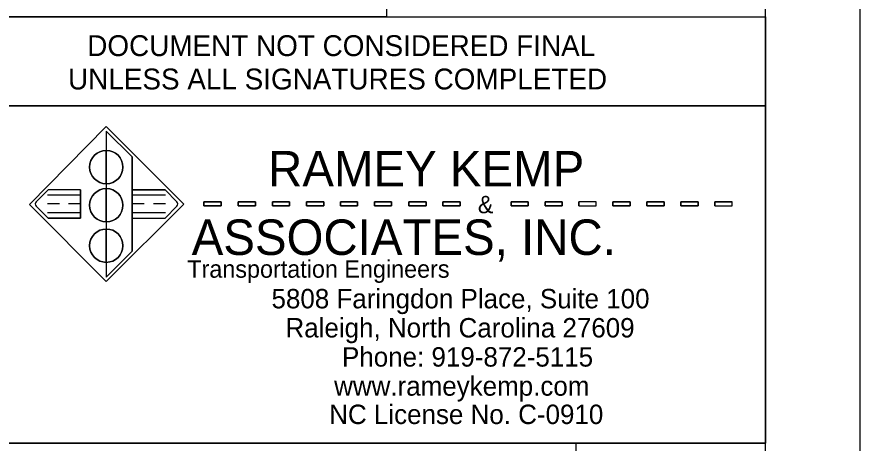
# Model space of a CAD drawing. Extents: x 573078 to 573116.9, y -55221.3 to -55199.3.
# Drawn here: x 573107.564 to 573112.014, y -55204.798 to -55202.549 of the extents above; entities that cross this region are included whole.
import ezdxf

# ---------------------------------------------------------------- set-up
doc = ezdxf.new("R2010")
doc.units = 0
for name, color, linetype in [('Old_Level_2', 7, 'Continuous'), ('Old_Level_4', 7, 'Continuous'), ('Sheet Plan CELL', 7, 'Continuous'), ('Sheet Plot Border Inside CELL', 7, 'Continuous'), ('Sheet Profile CELL', 7, 'Continuous'), ('Sheet Profile Grid Major CELL', 7, 'Continuous'), ('Sheet Sticker Exception Certification CELL', 7, 'Continuous')]:
    doc.layers.add(name, color=color, linetype=linetype)

msp = doc.modelspace()

# ---------------------------------------------------------------- linework, layer by layer
at = {"layer": 'Old_Level_2'}
for p, q in [((573108.0362, -55203.1533), (573108.0362, -55203.9224)), ((573108.0362, -55203.1533), (573108.1731, -55203.2886)), ((573108.1731, -55203.2886), (573108.1731, -55203.7849)), ((573107.7299, -55203.4617), (573107.666, -55203.5246)), ((573107.9008, -55203.4617), (573107.7299, -55203.4617)), ((573107.9008, -55203.4617), (573107.9008, -55203.6117)), ((573108.1731, -55203.4618), (573108.3461, -55203.4618)), ((573108.3461, -55203.4618), (573108.409, -55203.5252)), ((573107.7299, -55203.611), (573107.666, -55203.548)), ((573108.3461, -55203.611), (573108.409, -55203.5476)), ((573107.9008, -55203.611), (573107.7299, -55203.611)), ((573107.9008, -55203.6117), (573107.7299, -55203.6117)), ((573108.1731, -55203.611), (573108.3461, -55203.611)), ((573108.0362, -55203.9224), (573108.1731, -55203.7849))]:
    msp.add_line(p, q, dxfattribs=at)
for points in [[(573108.0362, -55203.8445), (573108.0362, -55203.9224), (573108.1731, -55203.7849), (573108.1731, -55203.5828), (573108.1731, -55203.5366), (573108.1731, -55203.4909), (573108.1731, -55203.2886), (573108.0362, -55203.1533), (573108.0362, -55203.2538)], [(573108.0362, -55203.4295), (573108.0362, -55203.2538)], [(573108.0362, -55203.4295), (573108.0362, -55203.4556)], [(573107.9008, -55203.5828), (573107.9008, -55203.5366), (573107.9008, -55203.4909), (573107.9008, -55203.4617), (573107.7299, -55203.4617), (573107.666, -55203.5246)], [(573108.0362, -55203.6314), (573108.0362, -55203.4556)], [(573108.4087, -55203.5248), (573108.3461, -55203.4618), (573108.1731, -55203.4618), (573108.1731, -55203.4909), (573108.1731, -55203.5366), (573108.1731, -55203.5828)], [(573108.5514, -55203.526), (573108.5514, -55203.547), (573108.6429, -55203.547), (573108.6429, -55203.526), (573108.5514, -55203.526)], [(573108.7328, -55203.526), (573108.7328, -55203.547), (573108.8227, -55203.547), (573108.8227, -55203.526), (573108.7328, -55203.526)], [(573108.9124, -55203.526), (573108.9124, -55203.547), (573109.0033, -55203.547), (573109.0033, -55203.526), (573108.9124, -55203.526)], [(573109.0924, -55203.526), (573109.0924, -55203.547), (573109.1832, -55203.547), (573109.1832, -55203.526), (573109.0924, -55203.526)], [(573109.2715, -55203.526), (573109.2715, -55203.547), (573109.3625, -55203.547), (573109.3625, -55203.526), (573109.2715, -55203.526)], [(573109.4506, -55203.526), (573109.4506, -55203.547), (573109.5416, -55203.547), (573109.5416, -55203.526), (573109.4506, -55203.526)], [(573109.6319, -55203.526), (573109.6319, -55203.547), (573109.7232, -55203.547), (573109.7232, -55203.526), (573109.6319, -55203.526)], [(573109.8116, -55203.526), (573109.8116, -55203.547), (573109.9027, -55203.547), (573109.9027, -55203.526), (573109.8116, -55203.526)], [(573110.1721, -55203.526), (573110.1721, -55203.547), (573110.2628, -55203.547), (573110.2628, -55203.526), (573110.1721, -55203.526)], [(573110.3512, -55203.526), (573110.3512, -55203.547), (573110.4421, -55203.547), (573110.4421, -55203.526), (573110.3512, -55203.526)], [(573110.6215, -55203.526), (573110.5305, -55203.526), (573110.5305, -55203.547), (573110.6215, -55203.547), (573110.6215, -55203.526)], [(573110.7099, -55203.526), (573110.7099, -55203.547), (573110.8009, -55203.547), (573110.8009, -55203.526), (573110.7099, -55203.526)], [(573110.8893, -55203.526), (573110.8893, -55203.547), (573110.9803, -55203.547), (573110.9803, -55203.526), (573110.8893, -55203.526)], [(573111.0687, -55203.526), (573111.0687, -55203.547), (573111.1597, -55203.547), (573111.1597, -55203.526), (573111.0687, -55203.526)], [(573111.2481, -55203.547), (573111.339, -55203.547), (573111.339, -55203.526), (573111.2481, -55203.526), (573111.2481, -55203.547)], [(573107.666, -55203.548), (573107.7299, -55203.6117), (573107.9008, -55203.6117), (573107.9008, -55203.5828)], [(573108.1731, -55203.5828), (573108.1731, -55203.611), (573108.3461, -55203.611), (573108.4087, -55203.548)], [(573108.0362, -55203.6314), (573108.0362, -55203.6687)], [(573108.0362, -55203.8445), (573108.0362, -55203.6687)]]:
    msp.add_lwpolyline(points, dxfattribs=at)
for centre, radius, start, end in [((573108.0362, -55203.3417), 0.0879, 90, 180), ((573108.0362, -55203.3417), 0.0879, 0, 90), ((573108.0362, -55203.3417), 0.0879, 180, 270), ((573108.0362, -55203.3417), 0.0879, 270, 0), ((573108.0362, -55203.5435), 0.0879, 90, 180), ((573108.0362, -55203.5435), 0.0879, 0, 90), ((573107.6775, -55203.5363), 0.0164, 134.5812, 225.4188), ((573107.6775, -55203.5363), 0.0164, 134.5812, 225.4188), ((573108.3971, -55203.5364), 0.0164, 315.2131, 44.7869), ((573108.3971, -55203.5364), 0.0164, 315.2131, 44.7869), ((573108.0362, -55203.5435), 0.0879, 180, 270), ((573108.0362, -55203.5435), 0.0879, 270, 0), ((573108.0362, -55203.7566), 0.0879, 90, 180), ((573108.0362, -55203.7566), 0.0879, 0, 90), ((573108.0362, -55203.7566), 0.0879, 180, 270), ((573108.0362, -55203.7566), 0.0879, 270, 0)]:
    msp.add_arc(centre, radius, start, end, dxfattribs=at)
at = {"layer": 'Old_Level_4'}
for p, q in [((573108.0353, -55203.1282), (573107.6305, -55203.5389)), ((573108.0353, -55203.1282), (573108.446, -55203.5369)), ((573107.9008, -55203.4909), (573107.7257, -55203.4909)), ((573108.3485, -55203.4909), (573108.1735, -55203.4909)), ((573108.0353, -55203.9457), (573107.6305, -55203.5389)), ((573107.789, -55203.5366), (573107.7257, -55203.5366)), ((573107.9008, -55203.5366), (573107.8369, -55203.5366)), ((573108.446, -55203.5369), (573108.0353, -55203.9457)), ((573108.2368, -55203.5366), (573108.1735, -55203.5366)), ((573108.3485, -55203.5366), (573108.2846, -55203.5366)), ((573110.5305, -55203.547), (573110.5305, -55203.526)), ((573110.6215, -55203.526), (573110.5305, -55203.526)), ((573110.6215, -55203.547), (573110.6215, -55203.526)), ((573111.2481, -55203.547), (573111.2481, -55203.526)), ((573111.2481, -55203.526), (573111.339, -55203.526)), ((573111.339, -55203.547), (573111.339, -55203.526)), ((573107.9008, -55203.5828), (573107.7257, -55203.5828)), ((573108.3485, -55203.5828), (573108.1735, -55203.5828)), ((573110.5305, -55203.547), (573110.6215, -55203.547)), ((573111.2481, -55203.547), (573111.339, -55203.547))]:
    msp.add_line(p, q, dxfattribs=at)
for points in [[(573108.0353, -55203.1282), (573107.6305, -55203.5389), (573108.0353, -55203.9457), (573108.446, -55203.5369), (573108.0353, -55203.1282)], [(573108.0362, -55203.2538), (573108.0362, -55203.4295)], [(573108.0362, -55203.4556), (573108.0362, -55203.6314)], [(573108.0362, -55203.6687), (573108.0362, -55203.8445)]]:
    msp.add_lwpolyline(points, dxfattribs=at)
for points in [[(573108.5514, -55203.526), (573108.6429, -55203.526), (573108.6429, -55203.547), (573108.5514, -55203.547)], [(573108.7328, -55203.526), (573108.8227, -55203.526), (573108.8227, -55203.547), (573108.7328, -55203.547)], [(573108.9124, -55203.526), (573109.0033, -55203.526), (573109.0033, -55203.547), (573108.9124, -55203.547)], [(573109.0924, -55203.526), (573109.1832, -55203.526), (573109.1832, -55203.547), (573109.0924, -55203.547)], [(573109.2715, -55203.526), (573109.3625, -55203.526), (573109.3625, -55203.547), (573109.2715, -55203.547)], [(573109.4506, -55203.526), (573109.5416, -55203.526), (573109.5416, -55203.547), (573109.4506, -55203.547)], [(573109.6319, -55203.526), (573109.7232, -55203.526), (573109.7232, -55203.547), (573109.6319, -55203.547)], [(573109.8116, -55203.526), (573109.9027, -55203.526), (573109.9027, -55203.547), (573109.8116, -55203.547)], [(573110.1721, -55203.526), (573110.2628, -55203.526), (573110.2628, -55203.547), (573110.1721, -55203.547)], [(573110.3512, -55203.526), (573110.4421, -55203.526), (573110.4421, -55203.547), (573110.3512, -55203.547)], [(573110.7099, -55203.526), (573110.8009, -55203.526), (573110.8009, -55203.547), (573110.7099, -55203.547)], [(573110.8893, -55203.526), (573110.9803, -55203.526), (573110.9803, -55203.547), (573110.8893, -55203.547)], [(573111.0687, -55203.526), (573111.1597, -55203.526), (573111.1597, -55203.547), (573111.0687, -55203.547)]]:
    msp.add_lwpolyline(points, close=True, dxfattribs=at)
for centre in [(573108.0362, -55203.3417), (573108.0362, -55203.5435), (573108.0362, -55203.7566)]:
    msp.add_circle(centre, 0.0879, dxfattribs=at)
for centre, start, end in [((573108.0362, -55203.3417), 0, 90), ((573108.0362, -55203.3417), 270, 0), ((573108.0362, -55203.5435), 0, 90), ((573108.0362, -55203.5435), 270, 0), ((573108.0362, -55203.7566), 0, 90), ((573108.0362, -55203.7566), 270, 0)]:
    msp.add_arc(centre, 0.0879, start, end, dxfattribs=at)
at = {"layer": 'Sheet Plan CELL'}
msp.add_lwpolyline([(573111.5139, -55204.7984), (573107.5142, -55204.7984), (573107.5142, -55203.0194), (573111.5139, -55203.0194)], close=True, dxfattribs=at)
at = {"layer": 'Sheet Plot Border Inside CELL'}
msp.add_lwpolyline([(573112.0142, -55199.2984), (573078.0142, -55199.2984), (573078.0142, -55221.2984), (573112.0142, -55221.2984)], close=True, dxfattribs=at)
at = {"layer": 'Sheet Profile CELL'}
for points in [[(573111.5142, -55199.7984), (573081.5142, -55199.7984), (573081.5142, -55220.7984), (573111.5142, -55220.7984)], [(573107.5142, -55200.2994), (573109.5142, -55200.2994), (573109.5142, -55202.5494), (573107.5142, -55202.5494)]]:
    msp.add_lwpolyline(points, close=True, dxfattribs=at)
at = {"layer": 'Sheet Profile Grid Major CELL'}
for points in [[(573110.5142, -55204.7984), (573110.5142, -55209.7984), (573111.5142, -55209.7984), (573111.5142, -55202.7984)], [(573107.5142, -55203.7984), (573081.5142, -55203.7984), (573081.5142, -55204.7984), (573111.5139, -55204.7984)]]:
    msp.add_lwpolyline(points, dxfattribs=at)
at = {"layer": 'Sheet Sticker Exception Certification CELL'}
for p, q in [((573107.5142, -55202.5494), (573111.5149, -55202.5494)), ((573111.5149, -55202.5494), (573111.5149, -55203.0194)), ((573111.5149, -55203.0194), (573107.5142, -55203.0194))]:
    msp.add_line(p, q, dxfattribs=at)

# ---------------------------------------------------------------- texts
at = {"layer": 'Old_Level_4'}
for s, height, p in [('RAMEY KEMP', 0.18711, (573108.89, -55203.4441)), ('&', 0.0919, (573109.9967, -55203.5855)), ('ASSOCIATES, INC.', 0.187109, (573108.4867, -55203.8055)), ('Transportation Engineers', 0.092176, (573108.4635, -55203.9257)), ('5808 Faringdon Place, Suite 100', 0.102418, (573108.908, -55204.0873)), ('Raleigh, North Carolina 27609', 0.102418, (573108.9816, -55204.2409)), ('Phone: 919-872-5115 ', 0.102418, (573109.28, -55204.3946)), ('www.rameykemp.com', 0.102418, (573109.2385, -55204.5482)), ('NC License No. C-0910', 0.102418, (573109.2125, -55204.6977))]:
    msp.add_text(s, height=height, dxfattribs=at).set_placement(p)
at = {"layer": 'Sheet Sticker Exception Certification CELL'}
for s, p in [('DOCUMENT NOT CONSIDERED FINAL', (573107.9356, -55202.7563)), ('UNLESS ALL SIGNATURES COMPLETED', (573107.8342, -55202.9323))]:
    msp.add_text(s, height=0.11, dxfattribs=at).set_placement(p)

doc.saveas('drawing.dxf')
